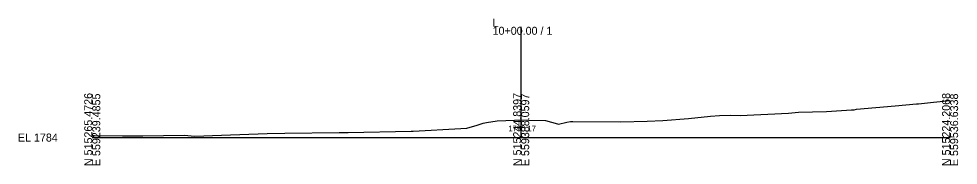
# Model space of a CAD drawing. Extents: x -26 to 1303, y -10 to 9545.
# Drawn here: x -25.7 to 302.8, y -9.7 to 41.6 of the extents above; entities that cross this region are included whole.
import ezdxf

# ---------------------------------------------------------------- set-up
doc = ezdxf.new("R2010")
doc.units = 0
for name, color, linetype in [('Exist Cross Section Cell', 7, 'Continuous'), ('Exist XS Center Line Elevation Label', 7, 'Continuous'), ('Exist XS Ground Line', 7, 'Continuous')]:
    doc.layers.add(name, color=color, linetype=linetype)

msp = doc.modelspace()

# ---------------------------------------------------------------- linework, layer by layer
at = {"layer": 'Exist Cross Section Cell'}
for p, q in [((150, 0), (150, 38.78)), ((0, 0), (150, 0)), ((150, 0), (300, 0))]:
    msp.add_line(p, q, dxfattribs=at)
at = {"layer": 'Exist XS Ground Line'}
for p, q in [((266.41, 9.65), (267.26, 9.95)), ((267.26, 9.95), (280.78, 11.12)), ((280.78, 11.12), (288.26, 11.76)), ((288.26, 11.76), (288.99, 11.81)), ((288.99, 11.81), (294.25, 12.34)), ((294.25, 12.34), (300, 12.93)), ((199.53, 5.94), (208.46, 6.61)), ((208.46, 6.61), (216.22, 7.45)), ((216.22, 7.45), (219.3, 7.74)), ((219.3, 7.74), (223.21, 7.82)), ((223.21, 7.82), (226.61, 7.77)), ((226.61, 7.77), (243.46, 8.56)), ((243.46, 8.56), (246.99, 8.87)), ((246.99, 8.87), (256.81, 9.06)), ((256.81, 9.06), (265.47, 9.67)), ((265.47, 9.67), (266.41, 9.65)), ((130.96, 3.24), (134.58, 4.36)), ((134.58, 4.36), (136.68, 5.09)), ((136.68, 5.09), (137.91, 5.26)), ((137.91, 5.26), (141.65, 5.88)), ((141.65, 5.88), (147.61, 6.08)), ((147.61, 6.08), (150.11, 6.17)), ((150.11, 6.17), (152.65, 6.13)), ((152.65, 6.13), (158.55, 5.99)), ((158.55, 5.99), (162.72, 4.78)), ((162.72, 4.78), (163.11, 4.7)), ((163.11, 4.7), (166.02, 5.35)), ((166.02, 5.35), (167.27, 5.65)), ((167.27, 5.65), (168.11, 5.65)), ((168.11, 5.65), (184.87, 5.48)), ((184.87, 5.48), (194.09, 5.71)), ((194.09, 5.71), (199.53, 5.94)), ((0, 0.71), (0.83, 0.69)), ((0.83, 0.69), (10.6, 0.55)), ((10.6, 0.55), (17.66, 0.59)), ((17.66, 0.59), (32.1, 0.81)), ((32.1, 0.81), (35.84, 0.54)), ((35.84, 0.54), (45.18, 0.86)), ((45.18, 0.86), (61.12, 1.42)), ((61.12, 1.42), (67.37, 1.58)), ((67.37, 1.58), (86.34, 1.77)), ((86.34, 1.77), (89.53, 1.8)), ((89.53, 1.8), (111.58, 2.19)), ((111.58, 2.19), (112.23, 2.22)), ((112.23, 2.22), (128.92, 3.11)), ((128.92, 3.11), (130.96, 3.24))]:
    msp.add_line(p, q, dxfattribs=at)

# ---------------------------------------------------------------- texts
at = {"layer": 'Exist Cross Section Cell'}
for s, p in [('L', (140, 38.78)), ('10+00.00 / 1', (140, 35.98)), ('EL 1784', (-26, -1.4))]:
    msp.add_text(s, height=2.8, dxfattribs=at).set_placement(p)
for s, p in [('N 515265.4726', (0, -10)), ('E 559239.4855', (2.8, -10)), ('N 515244.8397', (150, -10)), ('E 559388.0597', (152.8, -10)), ('N 515224.2068', (300, -10)), ('E 559536.6338', (302.8, -10))]:
    msp.add_text(s, height=2.8, rotation=90, dxfattribs=at).set_placement(p)
at = {"layer": 'Exist XS Center Line Elevation Label'}
msp.add_text('1790.17', height=2, dxfattribs=at).set_placement((145.51, 2.17))

doc.saveas('drawing.dxf')
